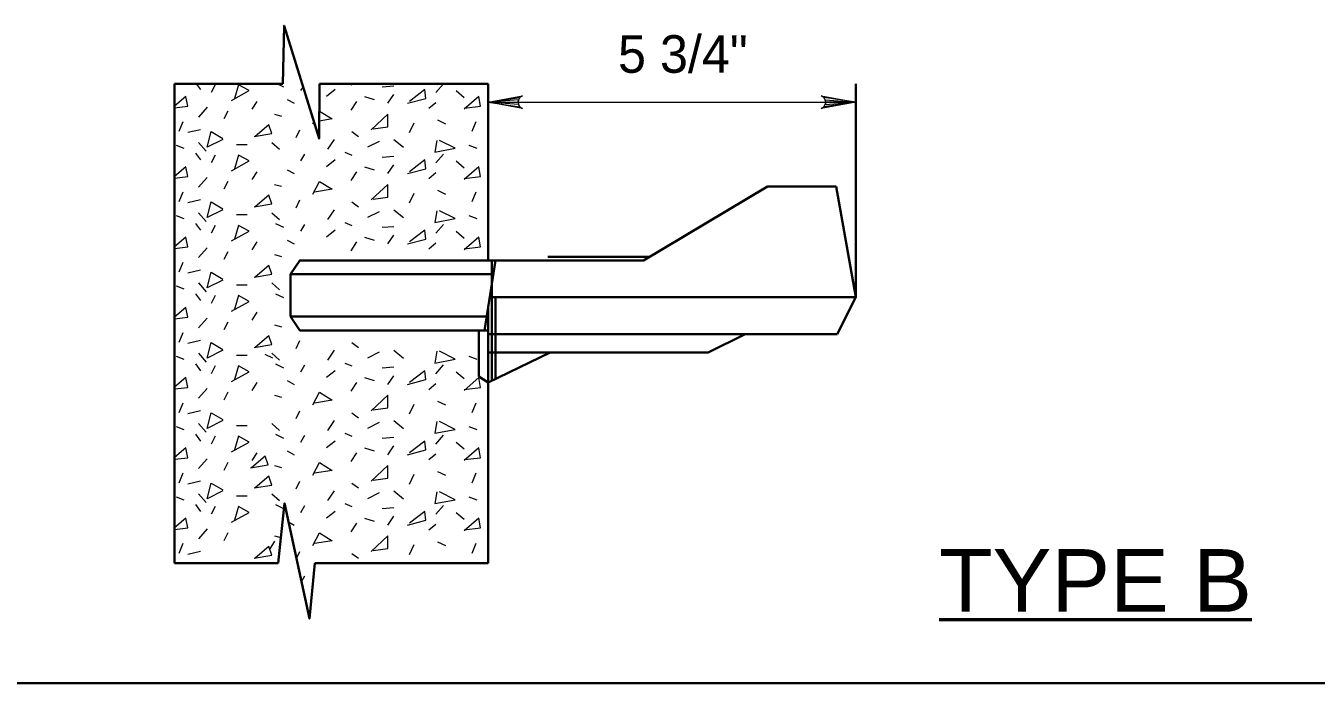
# Model space of a CAD drawing. Extents: x 15 to 140, y -57 to 117.
# Drawn here: x 78.51 to 113.5, y 57.95 to 75.77 of the extents above; entities that cross this region are included whole.
import ezdxf
from ezdxf.enums import TextEntityAlignment as Align

# ---------------------------------------------------------------- set-up
doc = ezdxf.new("R2010")
doc.units = 0
doc.header["$LTSCALE"] = 0.41
for name, color, linetype, lineweight in [('1', 7, 'Continuous', 35), ('10', 7, 'Continuous', 13), ('12', 7, 'Continuous', 53), ('13', 7, 'Continuous', 53), ('6', 7, 'Continuous', 13)]:
    doc.layers.add(name, color=color, linetype=linetype, lineweight=lineweight)

msp = doc.modelspace()

# ---------------------------------------------------------------- linework, layer by layer
at = {"layer": '1'}
for p, q in [((82.5406, 61.2025), (82.5406, 74.2025)), ((82.5406, 74.2025), (85.4788, 74.2025)), ((86.4692, 74.2025), (91.0406, 74.2025)), ((91.0406, 69.4129), (91.0406, 74.2025)), ((101.0093, 68.4129), (101.0093, 74.2025)), ((98.6226, 71.4129), (95.2593, 69.4129)), ((100.4804, 71.4129), (98.6226, 71.4129)), ((101.0093, 68.4129), (100.4804, 71.4129)), ((91.2406, 69.4129), (90.947, 67.5129)), ((91.1406, 69.4129), (91.1406, 66.1505)), ((95.4275, 69.5129), (92.6632, 69.5129)), ((85.6843, 69.0379), (85.6843, 67.8879)), ((91.1406, 69.0379), (85.6843, 69.0379)), ((101.0093, 68.4129), (91.0861, 68.4129)), ((91.2406, 68.4129), (91.2406, 66.1985)), ((101.0093, 68.4129), (100.5093, 67.4129)), ((91.0406, 67.8879), (85.6843, 67.8879)), ((85.6843, 67.8879), (85.9343, 67.5129)), ((91.0406, 68.1186), (91.0406, 66.1025)), ((91.0406, 67.5129), (85.9343, 67.5129)), ((90.7906, 67.5129), (90.7906, 66.2658)), ((100.5093, 67.4129), (91.0406, 67.4129)), ((98.0093, 67.4129), (97.0093, 66.9129)), ((97.0093, 66.9129), (91.0406, 66.9129)), ((91.0406, 66.1025), (92.729, 66.9129)), ((91.0406, 66.1025), (90.7906, 66.2658)), ((91.0406, 61.2025), (91.0406, 66.1025)), ((82.5406, 61.2025), (85.3453, 61.2025)), ((86.3409, 61.2025), (91.0406, 61.2025)), ((140.4342, 57.946), (15.0728, 57.946))]:
    msp.add_line(p, q, dxfattribs=at)
msp.add_lwpolyline([(85.6843, 69.0379), (85.9343, 69.4129), (91.1406, 69.4129), (91.1406, 69.0379)], close=True, dxfattribs=at)
msp.add_lwpolyline([(95.2593, 69.4129), (91.0406, 69.4129), (85.9343, 69.4129)], dxfattribs=at)
at = {"layer": '10'}
msp.add_line((91.0406, 73.7025), (101.0093, 73.7025), dxfattribs=at)
at = {"layer": '10', "lineweight": 35}
for points in [[(85.4788, 74.2025), (85.5084, 75.7743), (86.4578, 72.7176), (86.4692, 74.2025)], [(85.3453, 61.2025), (85.5184, 62.8283), (86.1978, 59.7005), (86.3409, 61.2025)]]:
    msp.add_lwpolyline(points, dxfattribs=at)
at = {"layer": '10'}
for points in [[(91.0406, 73.7025), (91.9727, 73.8773), (91.9008, 73.8275), (91.8638, 73.765), (91.8531, 73.7025), (91.8638, 73.64), (91.9008, 73.5775), (91.9727, 73.5277), (91.0406, 73.7025), (91.9008, 73.5775), (91.8638, 73.64), (91.0406, 73.7025), (91.8531, 73.7025), (91.8638, 73.765), (91.0406, 73.7025), (91.9008, 73.8275)], [(101.0093, 73.7025), (100.0773, 73.5277), (100.1491, 73.5775), (100.1861, 73.64), (100.1968, 73.7025), (100.1861, 73.765), (100.1491, 73.8275), (100.0773, 73.8773), (101.0093, 73.7025), (100.1491, 73.8275), (100.1861, 73.765), (101.0093, 73.7025), (100.1968, 73.7025), (100.1861, 73.64), (101.0093, 73.7025), (100.1491, 73.5775)]]:
    msp.add_lwpolyline(points, dxfattribs=at)
at = {"layer": '12'}
msp.add_line((103.2726, 59.6689), (111.7475, 59.6689), dxfattribs=at)
at = {"layer": '6'}
for p, q in [((85.8351, 74.6514), (85.8487, 74.6786)), ((83.1262, 74.2025), (83.2405, 74.0425)), ((85.3297, 74.2025), (85.4909, 74.1219)), ((87.2797, 74.2025), (87.3442, 74.1748)), ((89.6211, 73.963), (89.8329, 74.2013)), ((83.6376, 74.1748), (83.5317, 73.963)), ((85.9674, 74.016), (86.0239, 74.1147)), ((86.8941, 74.0425), (86.6558, 73.8571)), ((87.6884, 73.8571), (87.9531, 73.7777)), ((88.1649, 74.1219), (88.4826, 74.1484)), ((88.3238, 73.6718), (88.4826, 73.9101)), ((90.1771, 74.016), (90.3889, 73.8307)), ((83.4258, 73.5659), (83.1875, 73.3011)), ((84.6437, 73.513), (84.776, 73.7248)), ((85.5968, 73.7777), (85.7821, 73.6718)), ((87.4766, 73.7248), (87.3177, 73.4865)), ((89.4358, 73.5394), (89.6211, 73.6983)), ((82.7639, 73.1688), (82.658, 72.904)), ((83.9818, 73.46), (83.8759, 73.2482)), ((85.2526, 73.3806), (85.4379, 73.3276)), ((86.2852, 73.1158), (86.3162, 73.1735)), ((88.9062, 72.8775), (89.0386, 73.1423)), ((89.674, 73.2217), (89.8859, 73.1158)), ((90.7066, 73.1688), (90.6007, 72.904)), ((83.2405, 72.957), (82.8963, 72.8775)), ((85.8351, 72.7452), (85.941, 72.957)), ((87.3442, 72.904), (87.5295, 72.7716)), ((82.5786, 72.5334), (82.7904, 72.4539)), ((83.1875, 72.6128), (83.3993, 72.3745)), ((84.2201, 72.5598), (84.5113, 72.5598)), ((85.1732, 72.6128), (85.385, 72.4274)), ((86.8676, 72.6922), (86.6823, 72.4274)), ((88.0855, 72.6393), (87.7678, 72.4804)), ((88.4826, 72.6922), (88.7474, 72.4804)), ((90.5213, 72.5334), (90.7331, 72.4539)), ((83.1081, 72.3216), (83.2405, 72.1362)), ((83.6376, 72.2686), (83.5317, 72.0568)), ((85.9674, 72.1097), (86.0734, 72.2951)), ((86.8941, 72.1362), (86.6558, 71.9509)), ((87.1589, 72.348), (87.3442, 72.2686)), ((88.1649, 72.2156), (88.4826, 72.2421)), ((89.6211, 72.0568), (89.8329, 72.2951)), ((90.1771, 72.1097), (90.3889, 71.9244)), ((84.6437, 71.6067), (84.776, 71.8185)), ((85.5968, 71.8715), (85.7821, 71.7656)), ((87.4766, 71.8185), (87.3177, 71.5802)), ((87.6884, 71.9509), (87.9531, 71.8715)), ((88.3238, 71.7656), (88.4826, 72.0038)), ((89.4358, 71.6332), (89.6211, 71.792)), ((83.4258, 71.6597), (83.1875, 71.3949)), ((83.9818, 71.5537), (83.8759, 71.3419)), ((85.2526, 71.4743), (85.4379, 71.4214)), ((82.7639, 71.2625), (82.658, 70.9978)), ((83.2405, 71.0507), (82.8963, 70.9713)), ((85.8351, 70.8389), (85.941, 71.0507)), ((88.9062, 70.9713), (89.0386, 71.236)), ((89.674, 71.3155), (89.8859, 71.2096)), ((90.7066, 71.2625), (90.6007, 70.9978)), ((83.1875, 70.7065), (83.3993, 70.4682)), ((85.1732, 70.7065), (85.385, 70.5212)), ((86.8676, 70.786), (86.6823, 70.5212)), ((87.3442, 70.9978), (87.5295, 70.8654)), ((88.0855, 70.733), (87.7678, 70.5742)), ((88.4826, 70.786), (88.7474, 70.5742)), ((82.5786, 70.6271), (82.7904, 70.5477)), ((83.1081, 70.4153), (83.2405, 70.23)), ((83.6376, 70.3623), (83.5317, 70.1505)), ((84.2201, 70.6536), (84.5113, 70.6536)), ((85.2791, 70.4153), (85.4909, 70.3094)), ((85.9674, 70.2035), (86.0734, 70.3888)), ((87.1589, 70.4418), (87.3442, 70.3623)), ((88.1649, 70.3094), (88.4826, 70.3359)), ((89.6211, 70.1505), (89.8329, 70.3888)), ((90.5213, 70.6271), (90.7331, 70.5477)), ((86.8941, 70.23), (86.6558, 70.0446)), ((87.6884, 70.0446), (87.9531, 69.9652)), ((88.3238, 69.8593), (88.4826, 70.0976)), ((90.1771, 70.2035), (90.3889, 70.0182)), ((83.4258, 69.7534), (83.1875, 69.4886)), ((83.9818, 69.6475), (83.8759, 69.4357)), ((84.6437, 69.7005), (84.776, 69.9123)), ((85.5968, 69.9652), (85.7821, 69.8593)), ((87.4766, 69.9123), (87.3177, 69.674)), ((89.4358, 69.7269), (89.6211, 69.8858)), ((82.7639, 69.3563), (82.658, 69.0915)), ((85.2526, 69.5681), (85.4379, 69.5151)), ((85.6843, 69.0379), (85.9343, 69.4129)), ((83.2405, 69.1445), (82.8963, 69.065)), ((82.5786, 68.7209), (82.7904, 68.6414)), ((83.1875, 68.8003), (83.3993, 68.562)), ((84.2201, 68.7473), (84.5113, 68.7473)), ((85.1732, 68.8003), (85.385, 68.6149)), ((83.1081, 68.5091), (83.2405, 68.3237)), ((83.6376, 68.4561), (83.5317, 68.2443)), ((85.2791, 68.5091), (85.4909, 68.4031)), ((84.6437, 67.7942), (84.776, 68.006)), ((83.4258, 67.8472), (83.1875, 67.5824)), ((83.9818, 67.7412), (83.8759, 67.5294)), ((85.2526, 67.6618), (85.4379, 67.6089)), ((82.7639, 67.45), (82.658, 67.1853)), ((83.2405, 67.2382), (82.8963, 67.1588)), ((85.8351, 67.0264), (85.941, 67.2382)), ((87.3442, 67.1853), (87.5295, 67.0529)), ((83.1875, 66.894), (83.3993, 66.6557)), ((84.2201, 66.8411), (84.5113, 66.8411)), ((84.9874, 66.8734), (85.1992, 66.7674)), ((85.1732, 66.894), (85.385, 66.7087)), ((86.8676, 66.9735), (86.6823, 66.7087)), ((88.0855, 66.9205), (87.7678, 66.7617)), ((88.4826, 66.9735), (88.7474, 66.7617)), ((82.5786, 66.8146), (82.7904, 66.7352)), ((83.1081, 66.6028), (83.2405, 66.4175)), ((83.6376, 66.5498), (83.5317, 66.338)), ((85.2791, 66.6028), (85.4909, 66.4969)), ((85.9674, 66.391), (86.0734, 66.5763)), ((87.1589, 66.6293), (87.3442, 66.5498)), ((88.1649, 66.4969), (88.4826, 66.5234)), ((89.6211, 66.338), (89.8329, 66.5763)), ((90.5213, 66.8146), (90.7331, 66.7352)), ((85.5968, 66.1527), (85.7821, 66.0468)), ((86.8941, 66.4175), (86.6558, 66.2321)), ((87.6884, 66.2321), (87.9531, 66.1527)), ((88.3238, 66.0468), (88.4826, 66.2851)), ((90.1771, 66.391), (90.3889, 66.2057)), ((83.4258, 65.9409), (83.1875, 65.6761)), ((83.9818, 65.835), (83.8759, 65.6232)), ((84.6437, 65.888), (84.776, 66.0998)), ((87.4766, 66.0998), (87.3177, 65.8615)), ((89.4358, 65.9144), (89.6211, 66.0733)), ((82.7639, 65.5438), (82.658, 65.279)), ((85.2526, 65.7556), (85.4379, 65.7026)), ((88.9062, 65.2525), (89.0386, 65.5173)), ((89.674, 65.5967), (89.8859, 65.4908)), ((90.7066, 65.5438), (90.6007, 65.279)), ((83.2405, 65.332), (82.8963, 65.2525)), ((85.8351, 65.1202), (85.941, 65.332)), ((87.3442, 65.279), (87.5295, 65.1466)), ((82.5786, 64.9084), (82.7904, 64.8289)), ((83.1875, 64.9878), (83.3993, 64.7495)), ((84.2201, 64.9348), (84.5113, 64.9348)), ((85.1732, 64.9878), (85.385, 64.8024)), ((86.8676, 65.0672), (86.6823, 64.8024)), ((88.0855, 65.0143), (87.7678, 64.8554)), ((88.4826, 65.0672), (88.7474, 64.8554)), ((90.5213, 64.9084), (90.7331, 64.8289)), ((83.1081, 64.6966), (83.2405, 64.5112)), ((83.6376, 64.6436), (83.5317, 64.4318)), ((85.2791, 64.6966), (85.4909, 64.5906)), ((85.9674, 64.4847), (86.0734, 64.6701)), ((86.8941, 64.5112), (86.6558, 64.3259)), ((87.1589, 64.723), (87.3442, 64.6436)), ((88.1649, 64.5906), (88.4826, 64.6171)), ((89.6211, 64.4318), (89.8329, 64.6701)), ((90.1771, 64.4847), (90.3889, 64.2994)), ((83.4258, 64.0347), (83.1875, 63.7699)), ((84.6437, 63.9817), (84.776, 64.1935)), ((85.5968, 64.2465), (85.7821, 64.1406)), ((87.4766, 64.1935), (87.3177, 63.9552)), ((87.6884, 64.3259), (87.9531, 64.2465)), ((88.3238, 64.1406), (88.4826, 64.3788)), ((89.4358, 64.0082), (89.6211, 64.167)), ((83.9818, 63.9288), (83.8759, 63.7169)), ((85.2526, 63.8493), (85.4379, 63.7964)), ((89.674, 63.6905), (89.8859, 63.5846)), ((82.7639, 63.6375), (82.658, 63.3728)), ((83.2405, 63.4257), (82.8963, 63.3463)), ((85.8351, 63.2139), (85.941, 63.4257)), ((87.3442, 63.3728), (87.5295, 63.2404)), ((88.9062, 63.3463), (89.0386, 63.611)), ((90.7066, 63.6375), (90.6007, 63.3728)), ((82.5786, 63.0021), (82.7904, 62.9227)), ((83.1875, 63.0815), (83.3993, 62.8432)), ((84.2201, 63.0286), (84.5113, 63.0286)), ((85.1732, 63.0815), (85.385, 62.8962)), ((86.8676, 63.161), (86.6823, 62.8962)), ((88.0855, 63.108), (87.7678, 62.9492)), ((88.4826, 63.161), (88.7474, 62.9492)), ((90.5213, 63.0021), (90.7331, 62.9227)), ((83.1081, 62.7903), (83.2405, 62.605)), ((83.6376, 62.7373), (83.5317, 62.5255)), ((85.2791, 62.7903), (85.4909, 62.6844)), ((85.9674, 62.5785), (86.0734, 62.7638)), ((87.1589, 62.8168), (87.3442, 62.7373)), ((88.1649, 62.6844), (88.4826, 62.7109)), ((89.6211, 62.5255), (89.8329, 62.7638)), ((85.6284, 62.3222), (85.7821, 62.2343)), ((86.8941, 62.605), (86.6558, 62.4196)), ((87.4766, 62.2873), (87.3177, 62.049)), ((87.6884, 62.4196), (87.9531, 62.3402)), ((88.3238, 62.2343), (88.4826, 62.4726)), ((90.1771, 62.5785), (90.3889, 62.3932)), ((83.4258, 62.1284), (83.1875, 61.8636)), ((83.9818, 62.0225), (83.8759, 61.8107)), ((85.2526, 61.9431), (85.4191, 61.8955)), ((89.4358, 62.1019), (89.6211, 62.2608)), ((82.7639, 61.7313), (82.658, 61.4665)), ((85.1298, 61.589), (85.2622, 61.8008)), ((88.9062, 61.44), (89.0386, 61.7048)), ((89.674, 61.7842), (89.8859, 61.6783)), ((90.7066, 61.7313), (90.6007, 61.4665)), ((83.2405, 61.5195), (82.8963, 61.44)), ((85.8446, 61.3267), (85.941, 61.5195)), ((87.3442, 61.4665), (87.5295, 61.3341)), ((85.9814, 60.6967), (86.0734, 60.8576))]:
    msp.add_line(p, q, dxfattribs=at)
for points in [[(82.5406, 73.5505), (82.8963, 73.5924), (82.8433, 73.8571), (82.5406, 73.5948)], [(84.0877, 73.7512), (84.5642, 74.016), (84.273, 74.1748), (84.1671, 73.8042)], [(88.8533, 73.6718), (89.3563, 73.8042), (89.3299, 74.0425), (88.9062, 73.7248)], [(90.3889, 73.5394), (90.839, 73.5924), (90.786, 73.8571), (90.3889, 73.513)], [(86.4634, 73.4468), (86.4705, 73.46), (86.8147, 73.2482), (86.4614, 73.1893)], [(87.9266, 72.9834), (88.3238, 73.0364), (88.3238, 73.3806), (87.8737, 72.957)], [(83.8494, 72.6922), (83.4258, 72.4804), (83.5317, 72.904), (83.8494, 72.7187)], [(84.6966, 72.7716), (85.1732, 72.8511), (85.0938, 73.0893), (84.7231, 72.7716)], [(89.6476, 72.6657), (89.5946, 72.348), (90.1506, 72.4539), (89.727, 72.6657)], [(84.0877, 71.845), (84.5642, 72.1097), (84.273, 72.2686), (84.1671, 71.8979)], [(88.8533, 71.7656), (89.3563, 71.8979), (89.3299, 72.1362), (88.9062, 71.8185)], [(82.5406, 71.6443), (82.8963, 71.6861), (82.8433, 71.9509), (82.5406, 71.6885)], [(90.3889, 71.6332), (90.839, 71.6861), (90.786, 71.9509), (90.3889, 71.6067)], [(86.2852, 71.2096), (86.4705, 71.5537), (86.8147, 71.3419), (86.3381, 71.2625)], [(87.9266, 71.0772), (88.3238, 71.1301), (88.3238, 71.4743), (87.8737, 71.0507)], [(84.6966, 70.8654), (85.1732, 70.9448), (85.0938, 71.1831), (84.7231, 70.8654)], [(83.8494, 70.786), (83.4258, 70.5742), (83.5317, 70.9978), (83.8494, 70.8124)], [(89.6476, 70.7595), (89.5946, 70.4418), (90.1506, 70.5477), (89.727, 70.7595)], [(84.0877, 69.9387), (84.5642, 70.2035), (84.273, 70.3623), (84.1671, 69.9917)], [(82.5406, 69.738), (82.8963, 69.7799), (82.8433, 70.0446), (82.5406, 69.7823)], [(88.8533, 69.8593), (89.3563, 69.9917), (89.3299, 70.23), (88.9062, 69.9123)], [(90.3889, 69.7269), (90.839, 69.7799), (90.786, 70.0446), (90.3889, 69.7005)], [(83.8494, 68.8797), (83.4258, 68.6679), (83.5317, 69.0915), (83.8494, 68.9062)], [(84.6966, 68.9591), (85.1732, 69.0386), (85.0938, 69.2768), (84.7231, 68.9591)], [(84.0877, 68.0325), (84.5642, 68.2972), (84.273, 68.4561), (84.1671, 68.0854)], [(82.5406, 67.8318), (82.8963, 67.8736), (82.8433, 68.1384), (82.5406, 67.876)], [(83.8494, 66.9735), (83.4258, 66.7617), (83.5317, 67.1853), (83.8494, 66.9999)], [(84.6966, 67.0529), (85.1732, 67.1323), (85.0938, 67.3706), (84.7231, 67.0529)], [(89.6476, 66.947), (89.5946, 66.6293), (90.1506, 66.7352), (89.727, 66.947)], [(84.0877, 66.1262), (84.5642, 66.391), (84.273, 66.5498), (84.1671, 66.1792)], [(82.5406, 65.9255), (82.8963, 65.9674), (82.8433, 66.2321), (82.5406, 65.9698)], [(88.8533, 66.0468), (89.3563, 66.1792), (89.3299, 66.4175), (88.9062, 66.0998)], [(90.3889, 65.9144), (90.839, 65.9674), (90.786, 66.2321), (90.3889, 65.888)], [(86.2852, 65.4908), (86.4705, 65.835), (86.8147, 65.6232), (86.3381, 65.5438)], [(87.9266, 65.3584), (88.3238, 65.4114), (88.3238, 65.7556), (87.8737, 65.332)], [(83.8494, 65.0672), (83.4258, 64.8554), (83.5317, 65.279), (83.8494, 65.0937)], [(89.6476, 65.0407), (89.5946, 64.723), (90.1506, 64.8289), (89.727, 65.0407)], [(84.0877, 64.22), (84.5642, 64.4847), (84.273, 64.6436), (84.1671, 64.2729)], [(88.8533, 64.1406), (89.3563, 64.2729), (89.3299, 64.5112), (88.9062, 64.1935)], [(82.5406, 64.0193), (82.8963, 64.0611), (82.8433, 64.3259), (82.5406, 64.0635)], [(84.5994, 63.7846), (85.076, 63.864), (84.9965, 64.1023), (84.6259, 63.7846)], [(90.3889, 64.0082), (90.839, 64.0611), (90.786, 64.3259), (90.3889, 63.9817)], [(86.2852, 63.5846), (86.4705, 63.9288), (86.8147, 63.7169), (86.3381, 63.6375)], [(87.9266, 63.4522), (88.3238, 63.5051), (88.3238, 63.8493), (87.8737, 63.4257)], [(83.8494, 63.161), (83.4258, 62.9492), (83.5317, 63.3728), (83.8494, 63.1874)], [(84.6966, 63.2404), (85.1732, 63.3198), (85.0938, 63.5581), (84.7231, 63.2404)], [(89.6476, 63.1345), (89.5946, 62.8168), (90.1506, 62.9227), (89.727, 63.1345)], [(84.0877, 62.3137), (84.5642, 62.5785), (84.273, 62.7373), (84.1671, 62.3667)], [(82.5406, 62.113), (82.8963, 62.1549), (82.8433, 62.4196), (82.5406, 62.1573)], [(88.8533, 62.2343), (89.3563, 62.3667), (89.3299, 62.605), (88.9062, 62.2873)], [(90.3889, 62.1019), (90.839, 62.1549), (90.786, 62.4196), (90.3889, 62.0755)], [(86.2852, 61.6783), (86.4705, 62.0225), (86.8147, 61.8107), (86.3381, 61.7313)], [(87.9266, 61.5459), (88.3238, 61.5989), (88.3238, 61.9431), (87.8737, 61.5195)], [(84.6966, 61.3341), (85.1732, 61.4136), (85.0938, 61.6518), (84.7231, 61.3341)]]:
    msp.add_lwpolyline(points, dxfattribs=at)

# ---------------------------------------------------------------- texts
at = {"layer": '12', "width": 1.05}
msp.add_text('TYPE B', height=1.7, dxfattribs=at).set_placement((107.51, 59.8814), align=Align.CENTER)
at = {"layer": '13'}
msp.add_text('5 3/4"', height=1.02, dxfattribs=at).set_placement((96.3236, 74.5002), align=Align.CENTER)

doc.saveas('drawing.dxf')
